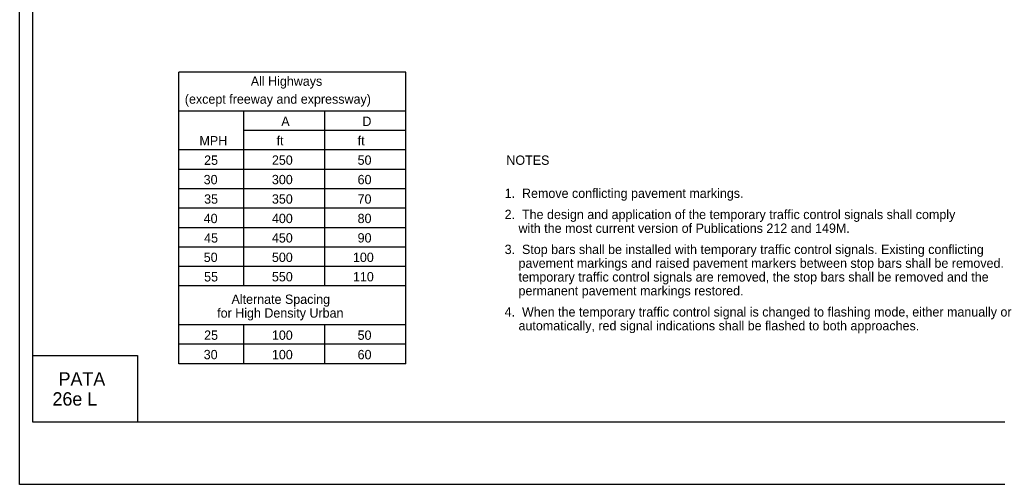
# Model space of a CAD drawing. Extents: x -14145 to -13662, y 30244 to 30661.
# Drawn here: x -13790.17 to -13768.19, y 30343.81 to 30354.26 of the extents above; entities that cross this region are included whole.
import ezdxf

# ---------------------------------------------------------------- set-up
doc = ezdxf.new("R2010")
doc.units = 0
for name, color, linetype in [('1', 7, 'Continuous'), ('10', 7, 'Continuous'), ('2', 7, 'Continuous'), ('3', 7, 'Continuous'), ('4', 7, 'Continuous'), ('61', 7, 'Continuous')]:
    doc.layers.add(name, color=color, linetype=linetype)

msp = doc.modelspace()

# ---------------------------------------------------------------- linework, layer by layer
at = {"layer": '1'}
for p, q in [((-13786.59, 30346.521), (-13786.59, 30353.077)), ((-13781.49, 30353.077), (-13786.59, 30353.077)), ((-13781.49, 30346.521), (-13781.49, 30353.077)), ((-13781.49, 30352.203), (-13786.592, 30352.203)), ((-13785.133, 30348.27), (-13785.133, 30352.203)), ((-13783.313, 30348.27), (-13783.313, 30352.203)), ((-13781.49, 30351.766), (-13785.133, 30351.766)), ((-13781.49, 30351.329), (-13786.592, 30351.329)), ((-13781.49, 30350.892), (-13786.592, 30350.892)), ((-13781.49, 30350.455), (-13786.592, 30350.455)), ((-13781.49, 30350.018), (-13786.592, 30350.018)), ((-13781.49, 30349.581), (-13786.592, 30349.581)), ((-13781.49, 30349.144), (-13786.592, 30349.144)), ((-13781.49, 30348.707), (-13786.592, 30348.707)), ((-13781.49, 30348.27), (-13786.592, 30348.27)), ((-13781.49, 30347.396), (-13786.593, 30347.396)), ((-13781.49, 30347.396), (-13786.593, 30347.396)), ((-13785.134, 30346.521), (-13785.134, 30347.396)), ((-13783.314, 30346.521), (-13783.314, 30347.396)), ((-13781.49, 30346.958), (-13786.593, 30346.958)), ((-13781.49, 30346.521), (-13786.59, 30346.521))]:
    msp.add_line(p, q, dxfattribs=at)
at = {"layer": '10'}
for p, q in [((-13789.874, 30345.207), (-13789.874, 30367.777)), ((-13789.874, 30346.707), (-13787.524, 30346.707)), ((-13787.524, 30346.707), (-13787.524, 30345.207)), ((-13758.422, 30345.207), (-13789.874, 30345.207))]:
    msp.add_line(p, q, dxfattribs=at)
at = {"layer": '61'}
msp.add_lwpolyline([(-13790.174, 30369.307), (-13757.174, 30369.307), (-13757.174, 30343.807), (-13790.174, 30343.807)], close=True, dxfattribs=at)

# ---------------------------------------------------------------- texts
at = {"layer": '2'}
for s, p in [('A', (-13784.29, 30351.868)), ('D', (-13782.467, 30351.868)), ('MPH', (-13786.13, 30351.431)), ('ft', (-13784.395, 30351.431)), ('ft', (-13782.574, 30351.431)), ('25', (-13786.025, 30350.994)), ('250', (-13784.501, 30350.995)), ('50', (-13782.575, 30350.995)), ('NOTES', (-13779.231, 30350.994)), ('30', (-13786.035, 30350.557)), ('300', (-13784.501, 30350.558)), ('60', (-13782.575, 30350.558)), ('1.  Remove conflicting pavement markings.', (-13779.27, 30350.25)), ('35', (-13786.025, 30350.12)), ('350', (-13784.501, 30350.121)), ('70', (-13782.575, 30350.121)), ('2.  The design and application of the temporary traffic control signals shall comply', (-13779.27, 30349.774)), ('40', (-13786.035, 30349.683)), ('400', (-13784.501, 30349.684)), ('80', (-13782.575, 30349.684)), ('    with the most current version of Publications 212 and 149M.', (-13779.27, 30349.464)), ('45', (-13786.025, 30349.246)), ('450', (-13784.501, 30349.247)), ('90', (-13782.575, 30349.247)), ('3.  Stop bars shall be installed with temporary traffic control signals. Existing conflicting', (-13779.27, 30348.988)), ('50', (-13786.034, 30348.809)), ('500', (-13784.501, 30348.81)), ('100', (-13782.68, 30348.81)), ('    pavement markings and raised pavement markers between stop bars shall be removed. After  ', (-13779.27, 30348.678)), ('55', (-13786.025, 30348.371)), ('550', (-13784.501, 30348.373)), ('110', (-13782.68, 30348.373)), ('    temporary traffic control signals are removed, the stop bars shall be removed and the', (-13779.27, 30348.368)), ('    permanent pavement markings restored.', (-13779.27, 30348.058)), ('4.  When the temporary traffic control signal is changed to flashing mode, either manually or ', (-13779.27, 30347.582)), ('    automatically, red signal indications shall be flashed to both approaches.', (-13779.27, 30347.272)), ('25', (-13786.025, 30347.059)), ('100', (-13784.501, 30347.059)), ('50', (-13782.575, 30347.059)), ('30', (-13786.034, 30346.622)), ('100', (-13784.501, 30346.622)), ('60', (-13782.575, 30346.622))]:
    msp.add_text(s, height=0.21, dxfattribs=at).set_placement(p)
at = {"layer": '3'}
for s, height, p in [('All Highways', 0.20979, (-13784.976, 30352.771)), ('(except freeway and expressway)', 0.21, (-13786.459, 30352.368)), ('Alternate Spacing ', 0.20979, (-13785.409, 30347.867)), ('for High Density Urban', 0.20979, (-13785.731, 30347.558))]:
    msp.add_text(s, height=height, dxfattribs=at).set_placement(p)
at = {"layer": '4'}
for s, p in [('PATA', (-13789.296, 30346.03)), ('26e L', (-13789.433, 30345.58))]:
    msp.add_text(s, height=0.3, dxfattribs=at).set_placement(p)

doc.saveas('drawing.dxf')
